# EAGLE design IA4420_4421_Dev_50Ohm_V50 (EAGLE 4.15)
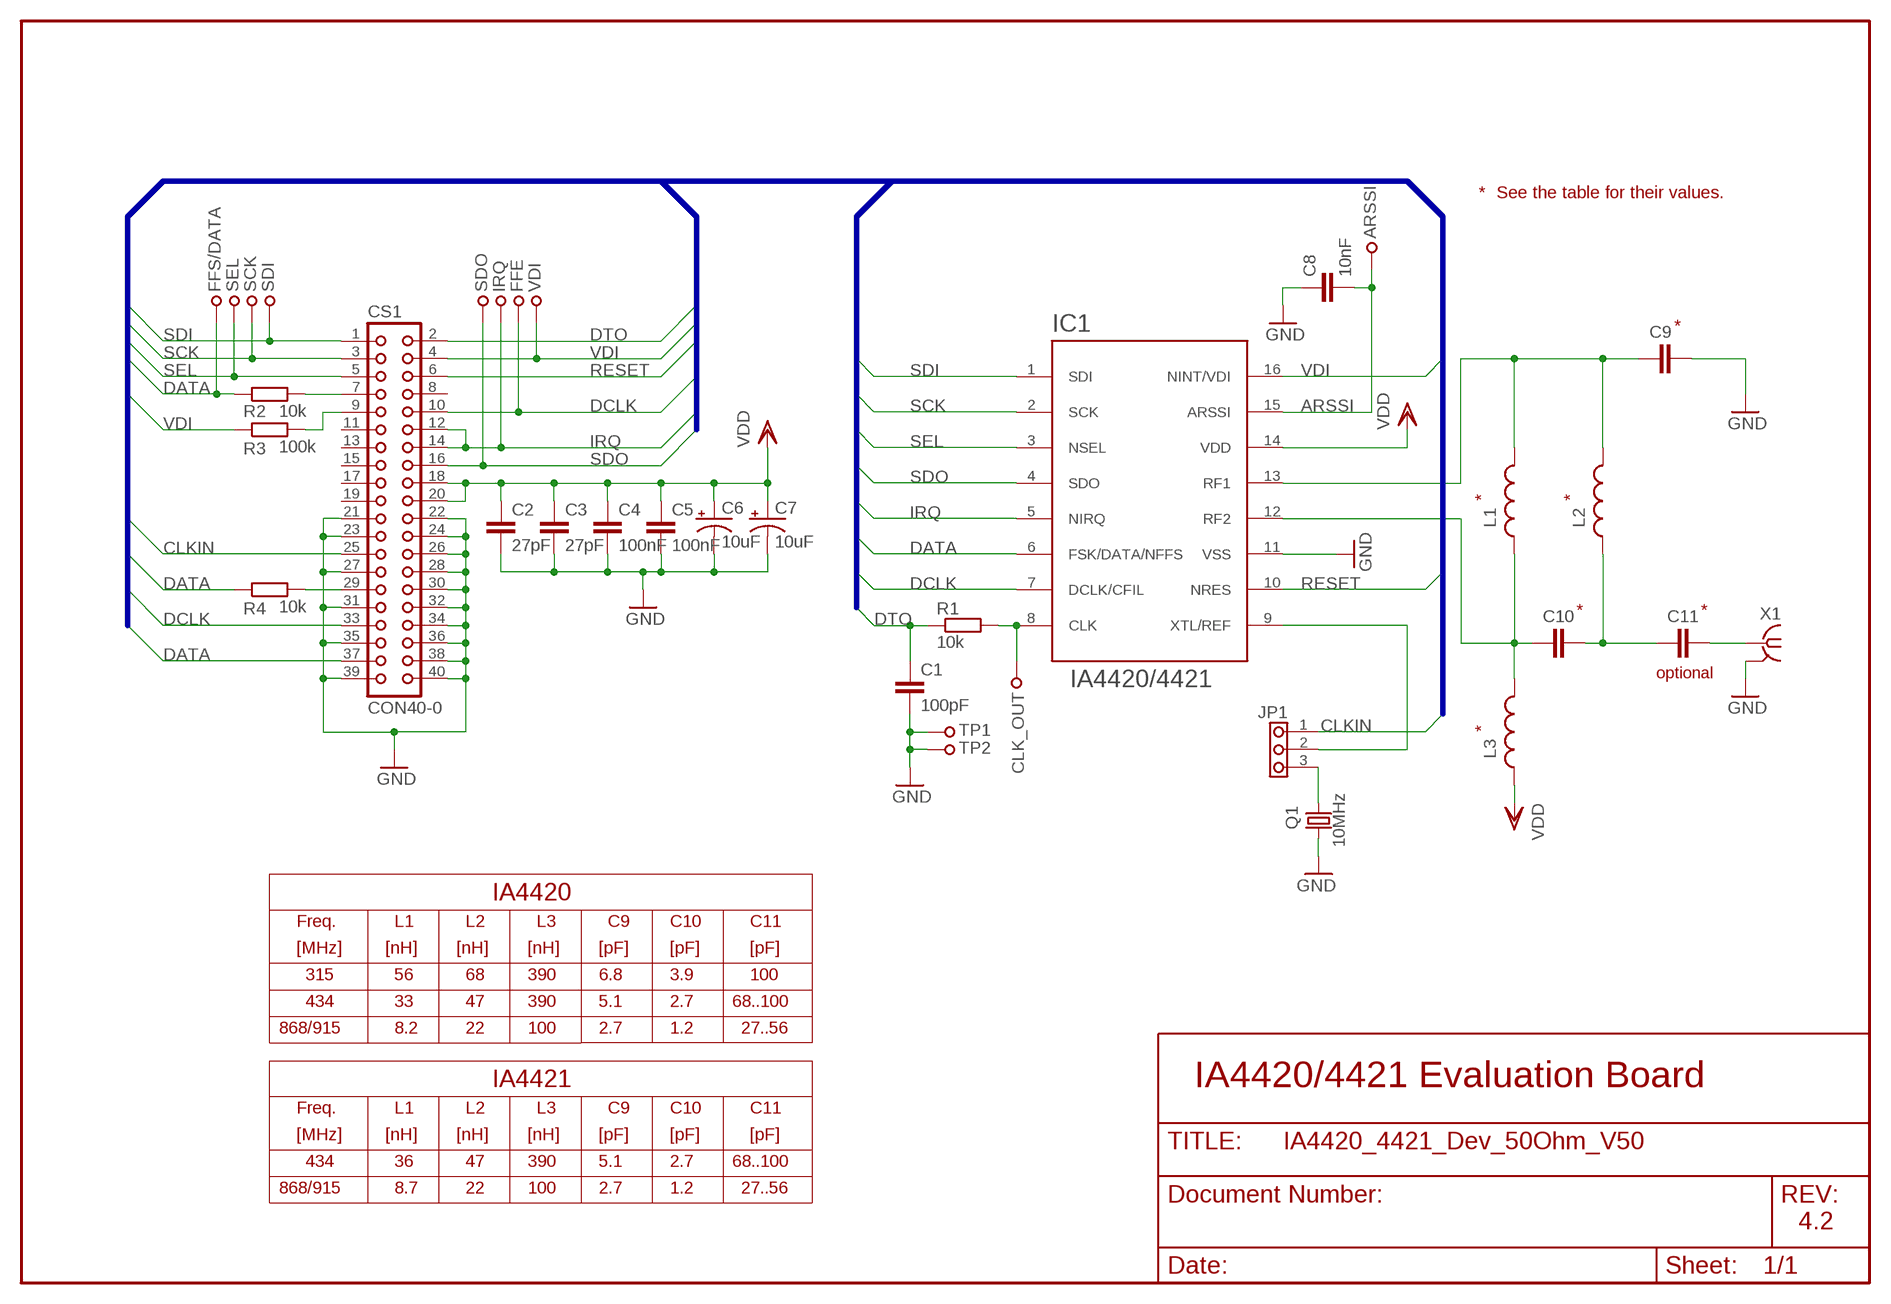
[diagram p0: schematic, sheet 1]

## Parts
ARSSI  TESTPOINT  TESTPOINT39MIL  [TESTPOINT1,0]
C1  100pF  C-EUC0603  [C0603]
C2  27pF  C-EUC0603  [C0603]
C3  27pF  C-EUC0603  [C0603]
C4  100nF  C-EUC0603  [C0603]
C5  100nF  C-EUC0603  [C0603]
C6  10uF  CPOL-USA/3216-18R  [A/3216-18R]
C7  10uF  CPOL-USA/3216-18R  [A/3216-18R]
C8  10nF  C-EUC0603  [C0603]
C9  C-EUC0603  [C0603]
C10  C-EUC0603  [C0603]
C11  C-EUC0603  [C0603]
CLK_OUT  TESTPOINT39MIL  [TESTPOINT1,0]
CS1  CON40-0  [PANDUIT-057-040-0-INTEGRATION]
FFE  TESTPOINT39MIL  [TESTPOINT1,0]
FFS/DATA  TESTPOINT39MIL  [TESTPOINT1,0]
IC1  IA4420/4421  TRIXIE-REVC  [TSSOP-16(NEW)]
IRQ  TESTPOINT39MIL  [TESTPOINT1,0]
JP1  JUMPER3  [PIN3]
L1  INDUCTCOILCRAFT-0603  [L1608]
L2  INDUCTCOILCRAFT-0603  [L1608]
L3  INDUCTCOILCRAFT-0603  [L1608]
Q1  10MHz  CRYTALSM49  [SM49]
R1  10k  R-EU_R0603  [R0603]
R2  10k  R-EU_R0603  [R0603]
R3  100k  R-EU_R0603  [R0603]
R4  10k  R-EU_R0603  [R0603]
SCK  TESTPOINT39MIL  [TESTPOINT1,0]
SDI  TESTPOINT39MIL  [TESTPOINT1,0]
SDO  TESTPOINT39MIL  [TESTPOINT1,0]
SEL  TESTPOINT39MIL  [TESTPOINT1,0]
TP1  TESTPOINT39MIL  [TESTPOINT1,0]
TP2  TESTPOINT39MIL  [TESTPOINT1,0]
VDI  TESTPOINT39MIL  [TESTPOINT1,0]
X1  BU-SMA-H  [BU-SMA-H]

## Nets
ARSSI: ARSSI.1 C8.2 IC1.15(ARSSI)
CLK_OUT: CLK_OUT.1 IC1.8(CLK) R1.2
CLKIN: CS1.25 JP1.1
DATA: CS1.37 FFS/DATA.1 IC1.6(FSK/DATA/NFFS) R2.1 R4.1
DCLK: CS1.10 CS1.33 FFE.1 IC1.7(DCLK/CFIL)
DTO: C1.1 CS1.2 R1.1
GND: C1.2 C2.2 C3.2 C4.2 C5.2 C6.- C7.- C8.1 C9.2 CS1.21 CS1.22 CS1.23 CS1.24 CS1.26 CS1.27 CS1.28 CS1.30 CS1.31 CS1.32 CS1.34 CS1.35 CS1.36 CS1.38 CS1.39 CS1.40 IC1.11(VSS) Q1.2 TP1.1 TP2.1 X1.2(GND)
IRQ: CS1.12 CS1.14 IC1.5(NIRQ) IRQ.1
N$1: CS1.7 R2.2
N$2: C10.1 IC1.12(RF2) L1.1 L3.2
N$3: C10.2 C11.1 L2.1
N$4: IC1.9(XTL/REF) JP1.2
N$5: CS1.29 R4.2
N$6: JP1.3 Q1.1
N$7: C11.2 X1.1
N$8: CS1.9 R3.2
N$11: C9.1 IC1.13(RF1) L1.2 L2.2
RESET: CS1.6 IC1.10(NRES)
SCK: CS1.3 IC1.2(SCK) SCK.1
SDI: CS1.1 IC1.1(SDI) SDI.1
SDO: CS1.16 IC1.4(SDO) SDO.1
SEL: CS1.5 IC1.3(NSEL) SEL.1
VDD: C2.1 C3.1 C4.1 C5.1 C6.+ C7.+ CS1.18 CS1.20 IC1.14(VDD) L3.1
VDI: CS1.4 IC1.16(NINT/VDI) R3.1 VDI.1
Unconnected: CS1.8 CS1.11 CS1.13 CS1.15 CS1.17 CS1.19

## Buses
SDI,SCK,SEL,SDO,IRQ,DATA,DCLK,VDI,RESET,ARSSI,DTO

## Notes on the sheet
- * | See the table for their values.
- *
- * | *
- * | *
- optional
- *
- IA4420
- Freq. | L1 | L2 | L3 | C9 | C10 | C11
- [MHz] | [nH] | [nH] | [nH] | [pF] | [pF] | [pF]
- 315 | 56 | 68 | 390 | 6.8 | 3.9 | 100
- 434 | 33 | 47 | 390 | 5.1 | 2.7 | 68..100
- 868/915 | 8.2 | 22 | 100 | 2.7 | 1.2 | 27..56
- IA4421 | IA4420/4421 Evaluation Board
- Freq. | L1 | L2 | L3 | C9 | C10 | C11
- [MHz] | [nH] | [nH] | [nH] | [pF] | [pF] | [pF]
- 434 | 36 | 47 | 390 | 5.1 | 2.7 | 68..100
- 868/915 | 8.7 | 22 | 100 | 2.7 | 1.2 | 27..56
- 4.2

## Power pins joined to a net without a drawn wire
GND: X1.3(GND) X1.4(GND) X1.5(GND)

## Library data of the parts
ARSSI CLK_OUT FFE FFS/DATA IRQ SCK SDI SDO SEL TP1 TP2 VDI = lve:TESTPOINT
C1-C5 C8-C11 = rcl:C-EU: CAPACITOR, European symbol
C6 C7 = rcl:CPOL-US: POLARIZED CAPACITOR, American symbol
CS1 = lve:CON40
IC1 = lve:TRIXIE-REVC
JP1 = lve:JUMPER3
L1-L3 = lve:INDUCT: SUMIDA
Q1 = crystal:CRYTAL: CRYSTAL
R1-R4 = rcl:R-EU_: RESISTOR, European symbol
X1 = lve:BU-SMA-H: FEMALE SMA CONNECTOR Radiall distributor RS 193-9325

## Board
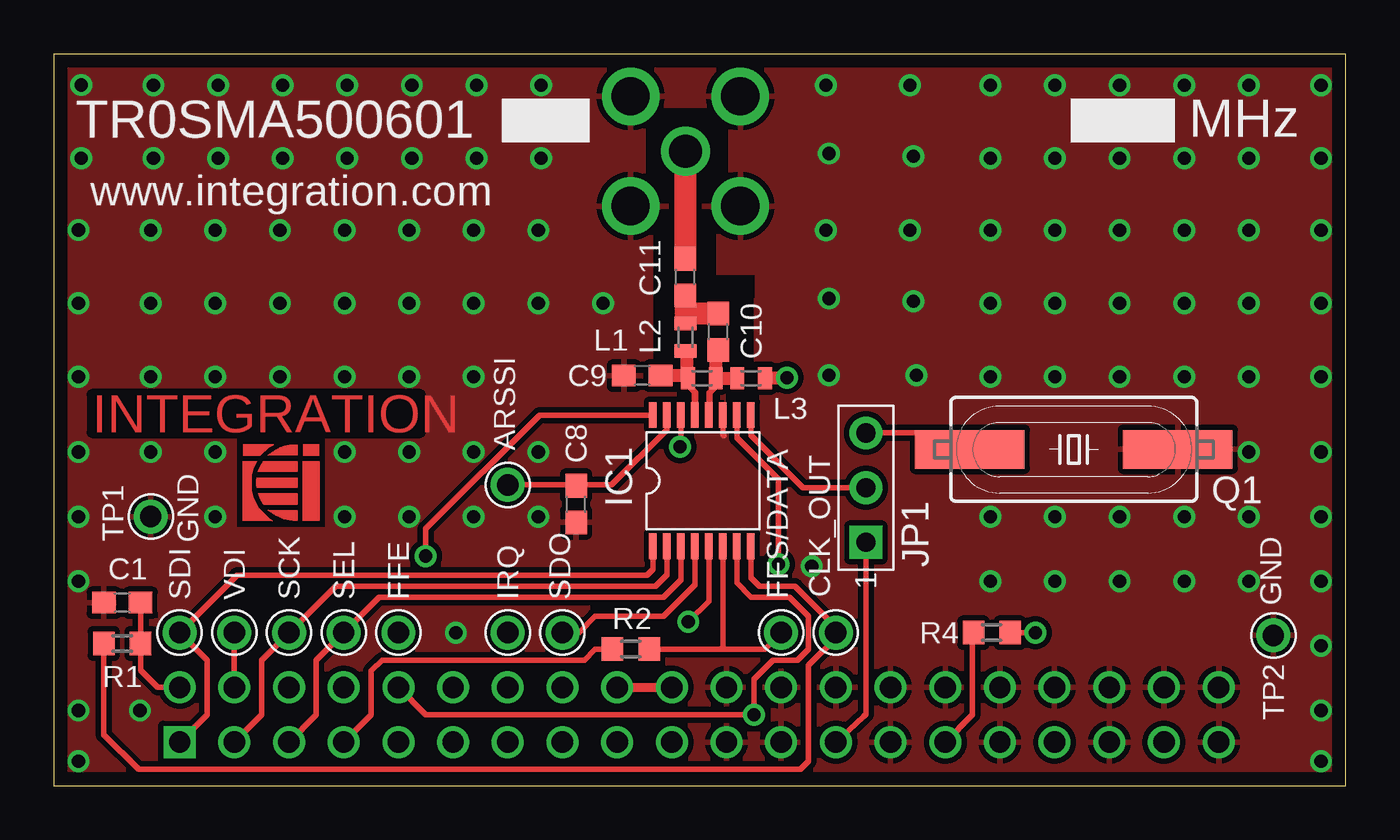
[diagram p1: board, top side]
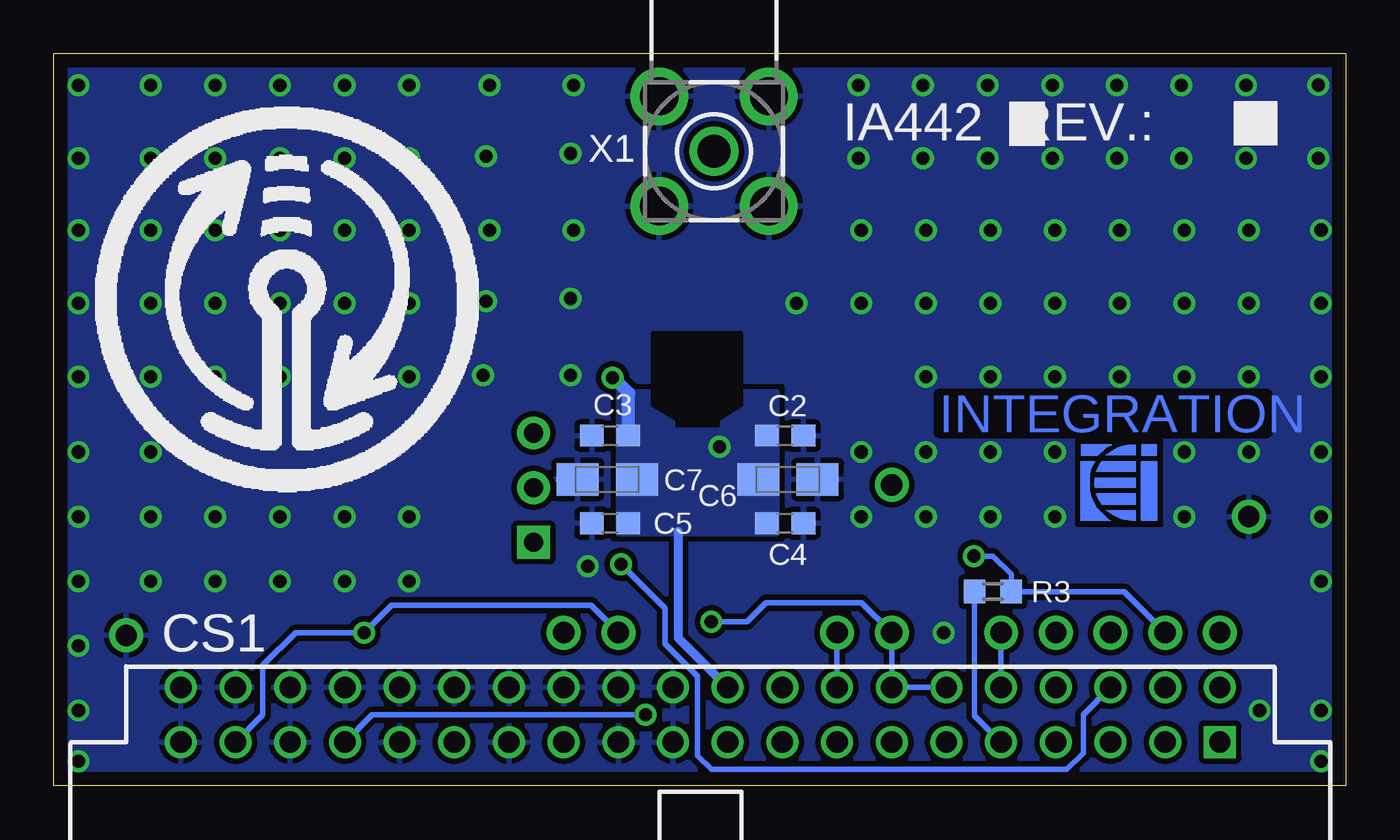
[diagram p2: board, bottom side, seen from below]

Size 60 x 33.98 mm. Coordinates in mm from the lower left corner, seen from the top.
Outline: 0,0 60,0 60,33.98 0,33.98 0,0
Copper layers (1*16): Top 0.035mm / dielectric 1.5mm / Bottom 0.035mm
Design rules "default_INTEGRATION": minimum track width 10mil, minimum drill 24mil, track to track 10mil, track to pad 10mil, pad to pad 10mil, via to via 10mil, smd to smd 10mil, copper to edge 25mil, drill to drill 8mil, minimum pad ring 8mil, minimum via ring 8mil, stop-mask expansion 4mil, vias tented up to drill 24mil, thermal gap 10mil
tRestrict: area 29.1,16.6 to 31.1,17.9; area 27.5,27.4 to 31.3,31.4; area 27.9,19.7 to 28.7,26.5; area 30,23.7 to 30.8,26.6; area 30,22.6 to 32.5,23.7; area 31.5,19.5 to 32.5,22.6; 3 lines
bRestrict: area 29.1,16.6 to 31.1,17.9; 9 lines

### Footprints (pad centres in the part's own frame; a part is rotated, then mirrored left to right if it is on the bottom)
TESTPOINT1,0 = drill 0.991 pad 1.575 round: 1 0,0
C0603 = smd 1.1 x 1: 1 -0.85,0; 2 0.85,0
A/3216-18R = smd 1.95 x 1.5: + 1.375,0; - -1.375,0
PANDUIT-057-040-0-INTEGRATION = drill 0.991 square: 1 -24.13,-1.27 | drill 0.991 round: 2 -24.13,-3.81; 3 -21.59,-1.27; 4 -21.59,-3.81; 5 -19.05,-1.27; 6 -19.05,-3.81; 7 -16.51,-1.27; 8 -16.51,-3.81; 9 -13.97,-1.27; 10 -13.97,-3.81; 11 -11.43,-1.27; 12 -11.43,-3.81; 13 -8.89,-1.27; 14 -8.89,-3.81; 15 -6.35,-1.27; 16 -6.35,-3.81; 17 -3.81,-1.27; 18 -3.81,-3.81; 19 -1.27,-1.27; 20 -1.27,-3.81; 21 1.27,-1.27; 22 1.27,-3.81; 23 3.81,-1.27; 24 3.81,-3.81; 25 6.35,-1.27; 26 6.35,-3.81; 27 8.89,-1.27; 28 8.89,-3.81; 29 11.43,-1.27; 30 11.43,-3.81; 31 13.97,-1.27; 32 13.97,-3.81; 33 16.51,-1.27; 34 16.51,-3.81; 35 19.05,-1.27; 36 19.05,-3.81; 37 21.59,-1.27; 38 21.59,-3.81; 39 24.13,-1.27; 40 24.13,-3.81
TSSOP-16(NEW) = smd 1.2 x 0.35: 1 -3.107,2.275; 2 -3.107,1.625; 3 -3.107,0.975; 4 -3.107,0.325; 5 -3.107,-0.325; 6 -3.107,-0.975; 7 -3.107,-1.625; 8 -3.107,-2.275; 9 2.993,-2.275; 10 2.993,-1.625; 11 2.993,-0.975; 12 2.993,-0.325; 13 2.993,0.325; 14 2.993,0.975; 15 2.993,1.625; 16 2.993,2.275
PIN3 = drill 0.889 pad 1.524 square: 1 -2.54,0 | drill 0.889 pad 1.524 round: 2 0,0; 3 2.54,0
L1608 = smd 0.64 x 1.02: 1 -0.64,0; 2 0.64,0
SM49 = smd 5.08 x 1.778: 1 -4.826,0; 2 4.826,0
R0603 = smd 1 x 1.1: 1 -0.85,0; 2 0.85,0
BU-SMA-H = drill 1.524 pad 2.286 round: 1 0,0 | drill 1.778 pad 2.667 round: 2 -2.55,2.55; 3 2.55,2.55; 4 2.55,-2.55; 5 -2.55,-2.55

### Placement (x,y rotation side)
ARSSI  21.08,13.97 0 top
C1  3.17,8.51 180 top
C2  26.04,16.26 0 bottom
C3  34.16,16.26 180 bottom
C4  26.04,12.19 0 bottom
C5  34.16,12.19 180 bottom
C6  25.91,14.22 180 bottom
C7  34.29,14.22 0 bottom
C8  24.26,13.08 90 top
C9  27.33,19.05 180 top
C10  30.86,21.08 90 top
C11  29.34,23.62 90 top
CLK_OUT  36.32,7.11 0 top
CS1  29.97,0.76 180 bottom
FFE  16,7.11 0 top
FFS/DATA  33.78,7.11 0 top
IC1  30.1,14.22 90 top
IRQ  21.08,7.11 0 top
JP1  37.72,13.84 90 top
L1  30.1,18.92 180 top
L2  29.34,20.83 270 top
L3  32.38,18.92 180 top
Q1  47.37,15.62 0 top
R1  3.17,6.6 180 top
R2  26.8,6.35 180 top
R3  16.38,9.02 180 bottom
R4  43.56,7.11 180 top
SCK  10.92,7.11 0 top
SDI  5.84,7.11 0 top
SDO  23.62,7.11 0 top
SEL  13.46,7.11 0 top
TP1  4.5,12.5 0 top
TP2  56.64,6.99 0 top
U$1  [INTEGRATION-HUNGARY]  10.54,14.1 0 top
U$2  [INTEGRATION-HUNGARY]  10.54,14.1 0 bottom
U$3  [TRANSCEIVE-ICON]  49.15,23.11 0 bottom
VDI  8.38,7.11 0 top
X1  29.34,29.46 90 bottom

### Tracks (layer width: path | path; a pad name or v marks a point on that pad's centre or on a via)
ARSSI
  Top 0.254: ARSSI.1 24.26,13.97 | 24.26,13.97 C8.2 | 24.26,13.97 25.91,13.97 28.47,16.54 IC1.15
CLK_OUT
  Top 0.254: R1.2 2.33,2.37 3.94,0.76 34.67,0.76 35.05,1.14 35.05,5.59 36.32,6.86 CLK_OUT.1 36.32,7.37 34.42,9.27 32.77,9.27 32.37,9.66 IC1.8
CLKIN
  Top 0.254: CS1.25 37.59,3.2 37.72,3.33 JP1.1
DATA  (via drill 0.61 pad 1.02)
  Top 0.254: 27.9,6.36 27.9,6.4 | R2.1 27.9,6.36 | 27.9,6.36 27.9,6.3 | 27.9,6.36 27.91,6.35 30.99,6.35 | 30.99,6.35 31.11,6.35 | 31.11,6.35 33.02,6.35 FFS/DATA.1 | 30.99,6.35 31.07,6.44 | v45.59,7.11 R4.1 | IC1.6 31.07,6.39 31.11,6.35
  Bottom 0.254: CS1.37 50.29,3.3 50.29,5.59 48.77,7.11 v45.59,7.11 44.32,8.38 35.05,8.38 FFS/DATA.1
DCLK  (via drill 0.61 pad 1.02)
  Top 0.254: CS1.10 17.27,3.3 v32.51,3.3 32.51,4.95 33.4,5.84 34.54,5.84 35.05,6.35 35.05,7.87 34.16,8.76 32.38,8.76 31.72,9.42 IC1.7
  Bottom 0.254: CS1.33 45.21,3.3 v32.51,3.3 | CS1.10 FFE.1
DTO
  Top 0.254: CS1.2 4.83,4.57 4.03,5.37 4.03,6.57 4.06,6.6 R1.1 4.03,8.47 4.06,8.51 C1.1
GND  (via drill 0.61 pad 1.02)
  Top 0.254: IC1.11 31.07,16.3 31.11,16.26
  other vias: 1.15,18.98 19.5,18.98 16.5,18.98 13.5,18.98 10.5,18.98 7.5,18.98 4.5,18.98 43.5,18.98 46.5,18.98 49.5,18.98 52.5,18.98 55.5,18.98 58.85,18.98 58.85,15.5 58.85,12.5 58.85,9.5 58.85,6.5 58.85,3.5 58.85,1.15 1.15,15.5 1.15,12.5 1.15,9.5 1.15,3.5 1.15,1.15 4.5,15.5 7.5,15.5 13.5,15.5 16.5,15.5 52.5,9.5 46.5,9.5 7.5,12.5 4,3.5 13.5,12.5 16.5,12.5 19.5,15.5 19.5,12.5 22.5,15.5 22.5,12.5 55.5,12.5 52.5,12.5 49.5,9.5 49.5,12.5 46.5,12.5 52.5,22.4 49.5,22.4 46.5,22.4 43.5,22.4 19.5,22.4 16.5,22.4 13.5,22.4 10.5,22.4 7.5,22.4 4.5,22.4 4.5,25.8 7.5,25.8 10.5,25.8 13.5,25.8 16.5,25.8 19.5,25.8 22.5,25.8 43.5,25.8 46.5,25.8 49.5,25.8 52.5,25.8 58.85,25.8 58.85,22.4 1.15,22.41 1.15,25.8 18.67,7.11 35.87,25.8 39.76,25.8 22.5,22.4 25.5,22.4 55.5,25.8 55.5,22.4 43.5,12.5 43.5,9.5 55.5,9.5 35.2,10.2 55.5,15.5 39.93,22.5 35.99,22.62 40.06,19.07 36.01,19.07 19.63,29.13 16.63,29.13 13.63,29.13 10.63,29.13 7.63,29.13 4.63,29.13 4.63,32.53 7.63,32.53 10.63,32.53 13.63,32.53 16.63,32.53 19.63,32.53 22.63,32.53 1.27,29.14 1.27,32.54 22.63,29.13 52.5,29.13 49.5,29.13 46.5,29.13 43.5,29.13 43.5,32.53 46.5,32.53 49.5,32.53 52.5,32.53 58.85,32.53 58.85,29.13 35.87,32.53 39.76,32.53 55.5,32.53 55.5,29.13 39.93,29.23 35.99,29.36
  pour Bottom (rank 2): 0,0 0,33.76 60,33.76 60,0
  pour Top (rank 2): 0,0 0,33.89 60,33.89 60,0
IRQ  (via drill 0.61 pad 1.02)
  Top 0.254: IC1.5 30.42,8.58 v29.46,7.62
  Bottom 0.254: CS1.12 CS1.14 IRQ.1 22.48,8.51 26.92,8.51 27.81,7.62 v29.46,7.62
N$1
  Top 0.254: R2.2 25.15,6.35 24.64,5.84 15.24,5.84 14.73,5.33 14.73,3.3 CS1.7
N$2
  Top 0.305: IC1.12 30.45,17.22 30.45,18.25 30.74,18.54 L1.1
  Top 0.61: C10.1 30.75,20.23 L1.1 | L1.1 | L1.1 L3.2
N$3
  Top 0.61: L2.1 29.35,21.75 | 29.3,22.77 29.3,22.8 | C11.1 29.3,22.77 | 29.35,22.1 29.3,22.1 29.3,22.77
  Top 1.016: 29.35,22.1 29.35,22 | 29.35,22 29.35,21.75 | 29.35,22 29.4,22 29.4,21.93 C10.2
N$4
  Top 0.254: JP1.2 34.8,13.84 32.37,16.27 IC1.9
N$5
  Top 0.254: R4.2 42.67,7.07 42.67,3.3 CS1.29
N$6
  Top 0.254: JP1.3 42.04,16.38 Q1.1
N$7
  Top 1.016: X1.1 29.34,29.44 C11.2
N$8
  Bottom 0.254: R3.2 17.23,3.26 CS1.9
N$11
  Top 0.305: L1.2 29.46,18.71 29.4,18.65 29.77,18.28 IC1.13
  Top 0.61: C9.1 29.4,19.05 29.4,19 | 29.4,19 29.4,18.92 L1.2 | L2.2 29.4,20.19 29.4,19
RESET  (via drill 0.61 pad 1.02)
  Top 0.254: IC1.10 31.72,16.16 33.66,14.22 v33.66,10.29
  Bottom 0.254: v33.66,10.29 31.62,8.26 31.62,6.6 30.1,5.08 30.1,1.4 29.46,0.76 12.95,0.76 12.19,1.52 12.19,3.3 CS1.6
SCK
  Top 0.254: CS1.3 9.65,3.3 9.65,5.84 SCK.1 13.08,9.27 27.94,9.27 28.47,9.8 IC1.2
SDI
  Top 0.254: CS1.1 7.11,3.3 7.11,5.84 SDI.1 8.51,9.78 27.56,9.78 27.82,10.04 IC1.1
SDO
  Top 0.254: SDO.1 24.38,7.11 25.15,7.87 28.32,7.87 29.77,9.33 IC1.4
  Bottom 0.254: CS1.16 SDO.1
SEL
  Top 0.254: CS1.5 12.19,3.3 12.19,5.84 SEL.1 15.11,8.76 28.32,8.76 29.12,9.57 IC1.3
VDD  (via drill 0.6, 0.61 pad 1.02)
  Top 0.254: IC1.14 29.12,15.79 v29.08,15.75
  Top 0.406: CS1.18 CS1.20
  Top 0.61: L3.1 34.05,18.92 v34.05,18.95
  Bottom 0.406: CS1.20 30.99,6.86 30.99,11.81
  Bottom 0.61: v34.05,18.95 34.05,18.9 33.95,18.9 33.3,18.25 33.3,16.35 33.25,16.3 33.29,16.26 C3.1
  pour Bottom (no thermals): 26.42,18.29 33.78,18.29 33.78,11.71 26.42,11.71
VDI  (via drill 0.61 pad 1.02)
  Top 0.254: CS1.4 VDI.1 | IC1.16 22.55,17.22 17.27,11.94 v17.27,10.67
  Bottom 0.254: v17.27,10.67 16.38,10.67 15.53,9.82 R3.1 10.29,9.02 VDI.1

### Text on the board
Top: INTEGRATION
Bottom: INTEGRATION
tPlace: TR0SMA500601 | MHz | www.integration.com | GND | 1 | GND
bPlace: IA442 REV.:
